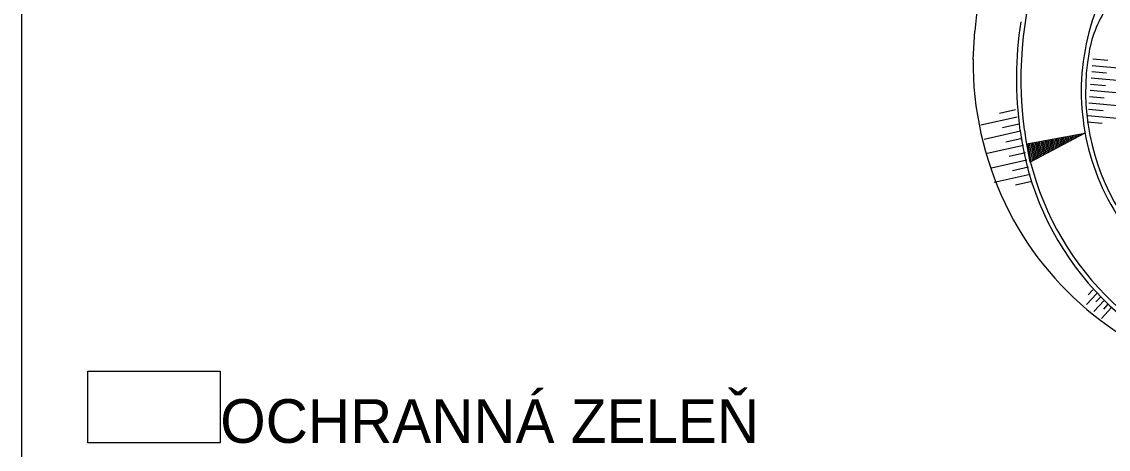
# Model space of a CAD drawing. Extents: x -439827 to -439102, y -1131353 to -1129707.
# Drawn here: x -439827 to -439640.5, y -1130540 to -1130466.6 of the extents above; entities that cross this region are included whole.
import ezdxf

# ---------------------------------------------------------------- set-up
doc = ezdxf.new("R2010")
doc.units = 0
for name, color, linetype in [('Vrstva 1', 7, 'Continuous'), ('Vrstva 52', 7, 'Continuous'), ('Vrstva 53', 7, 'Continuous'), ('Vrstva 59', 7, 'Continuous')]:
    doc.layers.add(name, color=color, linetype=linetype)

msp = doc.modelspace()

# ---------------------------------------------------------------- linework, layer by layer
at = {"layer": 'Vrstva 1'}
for points in [[(-439827.03, -1130069.63), (-439302.03, -1130069.63), (-439302.03, -1130812.13), (-439827.03, -1130812.13)], [(-439815.68, -1130526.61), (-439792.94, -1130526.61), (-439792.94, -1130538.9), (-439815.68, -1130538.9)]]:
    msp.add_lwpolyline(points, close=True, dxfattribs=at)
at = {"layer": 'Vrstva 52'}
for p in [(-439661.29, -1130447.84), (-439663.66, -1130473.1)]:
    msp.add_line(p, (-439663.38, -1130468.22), dxfattribs=at)
for points in [[(-439663.66, -1130473.04), (-439663.66, -1130474.81), (-439663.63, -1130476.22)], [(-439640.51, -1130518.79), (-439638.71, -1130520.05), (-439637.02, -1130521.08)]]:
    msp.add_lwpolyline(points, dxfattribs=at)
for centre, radius, start, end in [((-439590.43, -1130476.42), 65.05, 159.4012, 187.7621), ((-439605.62, -1130478.6), 39.5, 159.1565, 253.6594), ((-439624.08, -1130475.31), 20, 144.8351, 169.9106), ((-439590.43, -1130476.42), 65.8, 171.4418, 187.7621), ((-439605.62, -1130478.6), 38.75, 169.912, 253.6594), ((-439606.59, -1130473.34), 57.12, 182.9537, 208.6115), ((-439605.62, -1130478.6), 49.7, 187.6422, 253.6594), ((-439605.62, -1130478.6), 50.45, 187.6437, 253.6594), ((-439608.89, -1130474.14), 54.72, 209.0351, 234.6997)]:
    msp.add_arc(centre, radius, start, end, dxfattribs=at)
at = {"layer": 'Vrstva 53'}
for p, q in [((-439643.12, -1130473.01), (-439640.57, -1130473.24)), ((-439643.31, -1130475.16), (-439640.76, -1130475.39)), ((-439643.22, -1130474.12), (-439637.5, -1130474.63)), ((-439643.5, -1130477.32), (-439640.96, -1130477.55)), ((-439643.41, -1130476.23), (-439637.69, -1130476.75)), ((-439643.7, -1130479.48), (-439641.15, -1130479.7)), ((-439643.6, -1130478.35), (-439637.88, -1130478.86)), ((-439643.79, -1130480.54), (-439638.21, -1130481.05)), ((-439656.09, -1130482.99), (-439662.34, -1130484.4)), ((-439656.38, -1130481.72), (-439659.16, -1130482.35)), ((-439643.99, -1130482.7), (-439638.34, -1130483.21)), ((-439643.89, -1130481.63), (-439641.34, -1130481.86)), ((-439655.82, -1130484.19), (-439658.61, -1130484.82)), ((-439644.08, -1130483.79), (-439641.54, -1130484.01)), ((-439655.54, -1130485.42), (-439661.79, -1130486.83)), ((-439655.26, -1130486.66), (-439658.05, -1130487.29)), ((-439655, -1130487.84), (-439661.25, -1130489.25)), ((-439654.43, -1130490.36), (-439660.54, -1130491.73)), ((-439654.71, -1130489.13), (-439657.49, -1130489.76)), ((-439654.15, -1130491.6), (-439656.94, -1130492.23)), ((-439653.87, -1130492.83), (-439660.05, -1130494.22)), ((-439653.59, -1130494.07), (-439656.38, -1130494.7)), ((-439642.45, -1130513.28), (-439644.22, -1130515.14)), ((-439643.12, -1130512.64), (-439643.91, -1130513.48)), ((-439641.18, -1130514.48), (-439642.94, -1130516.34)), ((-439641.82, -1130513.87), (-439642.61, -1130514.7)), ((-439640.52, -1130515.1), (-439641.31, -1130515.93)), ((-439639.9, -1130515.69), (-439641.66, -1130517.55))]:
    msp.add_line(p, q, dxfattribs=at)
at = {"layer": 'Vrstva 59'}
for p, q in [((-439652.07, -1130487.15), (-439651.65, -1130489.54)), ((-439651.82, -1130487.1), (-439651.42, -1130489.42)), ((-439651.58, -1130487.05), (-439651.18, -1130489.29)), ((-439651.33, -1130487.01), (-439650.95, -1130489.17)), ((-439651.09, -1130486.96), (-439650.72, -1130489.04)), ((-439650.84, -1130486.92), (-439650.49, -1130488.92)), ((-439650.59, -1130486.87), (-439650.26, -1130488.8)), ((-439650.35, -1130486.83), (-439650.02, -1130488.67)), ((-439650.1, -1130486.78), (-439649.79, -1130488.55)), ((-439649.86, -1130486.73), (-439649.56, -1130488.43)), ((-439649.61, -1130486.69), (-439649.33, -1130488.3)), ((-439649.37, -1130486.64), (-439649.09, -1130488.18)), ((-439649.12, -1130486.6), (-439648.86, -1130488.05)), ((-439648.87, -1130486.55), (-439648.63, -1130487.93)), ((-439648.63, -1130486.5), (-439648.4, -1130487.81)), ((-439648.38, -1130486.46), (-439648.17, -1130487.68)), ((-439648.14, -1130486.41), (-439647.93, -1130487.56)), ((-439647.89, -1130486.37), (-439647.7, -1130487.44)), ((-439647.65, -1130486.32), (-439647.47, -1130487.31)), ((-439647.4, -1130486.28), (-439647.24, -1130487.19)), ((-439647.15, -1130486.23), (-439647.01, -1130487.07)), ((-439646.91, -1130486.18), (-439646.77, -1130486.94)), ((-439646.66, -1130486.14), (-439646.54, -1130486.82)), ((-439646.42, -1130486.09), (-439646.31, -1130486.69)), ((-439646.17, -1130486.05), (-439646.08, -1130486.57)), ((-439645.92, -1130486), (-439645.85, -1130486.45)), ((-439645.68, -1130485.96), (-439645.61, -1130486.32)), ((-439645.43, -1130485.91), (-439645.38, -1130486.2)), ((-439645.19, -1130485.86), (-439645.15, -1130486.08)), ((-439644.94, -1130485.82), (-439644.92, -1130485.95)), ((-439644.7, -1130485.77), (-439644.69, -1130485.83)), ((-439654.28, -1130487.56), (-439653.74, -1130490.65)), ((-439654.04, -1130487.51), (-439653.5, -1130490.53)), ((-439653.79, -1130487.47), (-439653.27, -1130490.4)), ((-439653.54, -1130487.42), (-439653.04, -1130490.28)), ((-439653.3, -1130487.37), (-439652.81, -1130490.16)), ((-439653.05, -1130487.33), (-439652.58, -1130490.03)), ((-439652.81, -1130487.28), (-439652.34, -1130489.91)), ((-439652.56, -1130487.24), (-439652.11, -1130489.79)), ((-439652.32, -1130487.19), (-439651.88, -1130489.66))]:
    msp.add_line(p, q, dxfattribs=at)
msp.add_lwpolyline([(-439654.47, -1130487.59), (-439644.52, -1130485.74), (-439653.89, -1130490.73)], close=True, dxfattribs=at)

# ---------------------------------------------------------------- texts
at = {"layer": 'Vrstva 1'}
msp.add_text('OCHRANNÁ ZELEŇ', height=7.5, dxfattribs=at).set_placement((-439792.94, -1130538.9))

doc.saveas('drawing.dxf')
